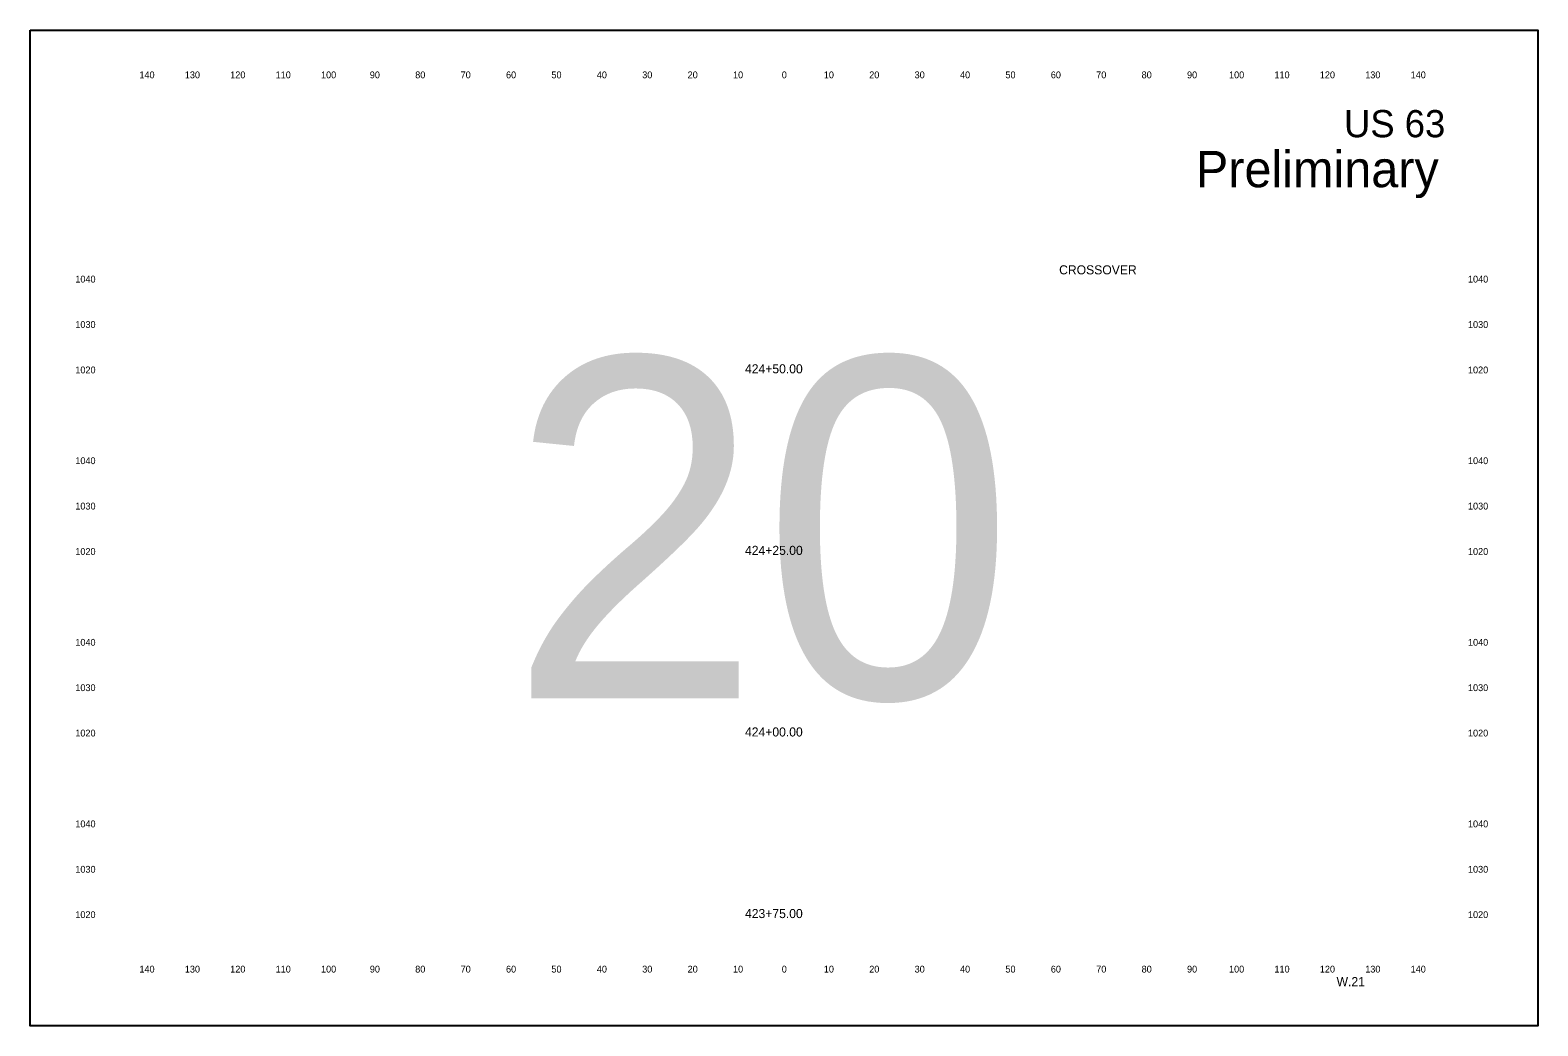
# Model space of a CAD drawing. Extents: x 10123 to 17295, y 9730 to 10181.
# Drawn here: x 16963.2 to 17295.3, y 9730.3 to 9949.6 of the extents above; entities that cross this region are included whole.
import ezdxf

# ---------------------------------------------------------------- set-up
doc = ezdxf.new("R2010")
doc.units = 0
for name, color, linetype in [('dsnTextCpn', 7, 'Continuous'), ('dsnTextCpnTitleSheetLocDesc', 7, 'Continuous'), ('dsnTextCpnTitleSheetPIN', 7, 'Continuous'), ('dsnTextCpnTitleSheetWorkType', 7, 'Continuous')]:
    doc.layers.add(name, color=color, linetype=linetype)

msp = doc.modelspace()

# ---------------------------------------------------------------- linework, layer by layer
at = {"layer": 'dsnTextCpnTitleSheetWorkType'}
msp.add_lwpolyline([(16963.21, 9949.6), (17295.29, 9949.6), (17295.29, 9730.26), (16963.21, 9730.26)], close=True, dxfattribs=at)

# ---------------------------------------------------------------- texts
at = {"layer": 'dsnTextCpn'}
for s, height, p in [('140', 1.5, (16987.27, 9939)), ('130', 1.5, (16997.27, 9939)), ('120', 1.5, (17007.27, 9939)), ('110', 1.5, (17017.27, 9939)), ('100', 1.5, (17027.27, 9939)), ('90', 1.5, (17038.02, 9939)), ('80', 1.5, (17048.02, 9939)), ('70', 1.5, (17058.02, 9939)), ('60', 1.5, (17068.02, 9939)), ('50', 1.5, (17078.02, 9939)), ('40', 1.5, (17088.02, 9939)), ('30', 1.5, (17098.02, 9939)), ('20', 1.5, (17108.02, 9939)), ('10', 1.5, (17118.02, 9939)), ('0', 1.5, (17128.76, 9939)), ('0', 1.5, (17128.76, 9939)), ('10', 1.5, (17138.02, 9939)), ('20', 1.5, (17148.02, 9939)), ('30', 1.5, (17158.02, 9939)), ('40', 1.5, (17168.02, 9939)), ('50', 1.5, (17178.02, 9939)), ('60', 1.5, (17188.02, 9939)), ('70', 1.5, (17198.02, 9939)), ('80', 1.5, (17208.02, 9939)), ('90', 1.5, (17218.02, 9939)), ('100', 1.5, (17227.27, 9939)), ('110', 1.5, (17237.27, 9939)), ('120', 1.5, (17247.27, 9939)), ('130', 1.5, (17257.27, 9939)), ('140', 1.5, (17267.27, 9939)), ('US 63', 6, (17252.6, 9926)), ('CROSSOVER', 2, (17189.85, 9895.8)), ('1040', 1.5, (16973.15, 9894)), ('1040', 1.5, (17279.9, 9894)), ('1030', 1.5, (16973.15, 9884)), ('1030', 1.5, (17279.9, 9884)), ('1020', 1.5, (16973.15, 9874)), ('424+50.00', 2, (17120.66, 9874)), ('1020', 1.5, (17279.9, 9874)), ('1040', 1.5, (16973.15, 9854)), ('1040', 1.5, (17279.9, 9854)), ('1030', 1.5, (16973.15, 9844)), ('1030', 1.5, (17279.9, 9844)), ('1020', 1.5, (16973.15, 9834)), ('424+25.00', 2, (17120.66, 9834)), ('1020', 1.5, (17279.9, 9834)), ('1040', 1.5, (16973.15, 9814)), ('1040', 1.5, (17279.9, 9814)), ('1030', 1.5, (16973.15, 9804)), ('1030', 1.5, (17279.9, 9804)), ('1020', 1.5, (16973.15, 9794)), ('424+00.00', 2, (17120.66, 9794)), ('1020', 1.5, (17279.9, 9794)), ('1040', 1.5, (16973.15, 9774)), ('1040', 1.5, (17279.9, 9774)), ('1030', 1.5, (16973.15, 9764)), ('1030', 1.5, (17279.9, 9764)), ('1020', 1.5, (16973.15, 9754)), ('423+75.00', 2, (17120.66, 9754)), ('1020', 1.5, (17279.9, 9754)), ('140', 1.5, (16987.27, 9742)), ('130', 1.5, (16997.27, 9742)), ('120', 1.5, (17007.27, 9742)), ('110', 1.5, (17017.27, 9742)), ('100', 1.5, (17027.27, 9742)), ('90', 1.5, (17038.02, 9742)), ('80', 1.5, (17048.02, 9742)), ('70', 1.5, (17058.02, 9742)), ('60', 1.5, (17068.02, 9742)), ('50', 1.5, (17078.02, 9742)), ('40', 1.5, (17088.02, 9742)), ('30', 1.5, (17098.02, 9742)), ('20', 1.5, (17108.02, 9742)), ('10', 1.5, (17118.02, 9742)), ('0', 1.5, (17128.76, 9742)), ('0', 1.5, (17128.76, 9742)), ('10', 1.5, (17138.02, 9742)), ('20', 1.5, (17148.02, 9742)), ('30', 1.5, (17158.02, 9742)), ('40', 1.5, (17168.02, 9742)), ('50', 1.5, (17178.02, 9742)), ('60', 1.5, (17188.02, 9742)), ('70', 1.5, (17198.02, 9742)), ('80', 1.5, (17208.02, 9742)), ('90', 1.5, (17218.02, 9742)), ('100', 1.5, (17227.27, 9742)), ('110', 1.5, (17237.27, 9742)), ('120', 1.5, (17247.27, 9742)), ('130', 1.5, (17257.27, 9742)), ('140', 1.5, (17267.27, 9742))]:
    msp.add_text(s, height=height, dxfattribs=at).set_placement(p)
at = {"layer": 'dsnTextCpnTitleSheetLocDesc'}
msp.add_text('Preliminary', height=8, dxfattribs=at).set_placement((17219.97, 9915))
at = {"layer": 'dsnTextCpnTitleSheetPIN'}
msp.add_text('W.21', height=2, dxfattribs=at).set_placement((17250.96, 9739))
at = {"layer": 'dsnTextCpnTitleSheetWorkType'}
msp.add_text('20', height=75, dxfattribs=at).set_placement((17068.55, 9802.43))

doc.saveas('drawing.dxf')
